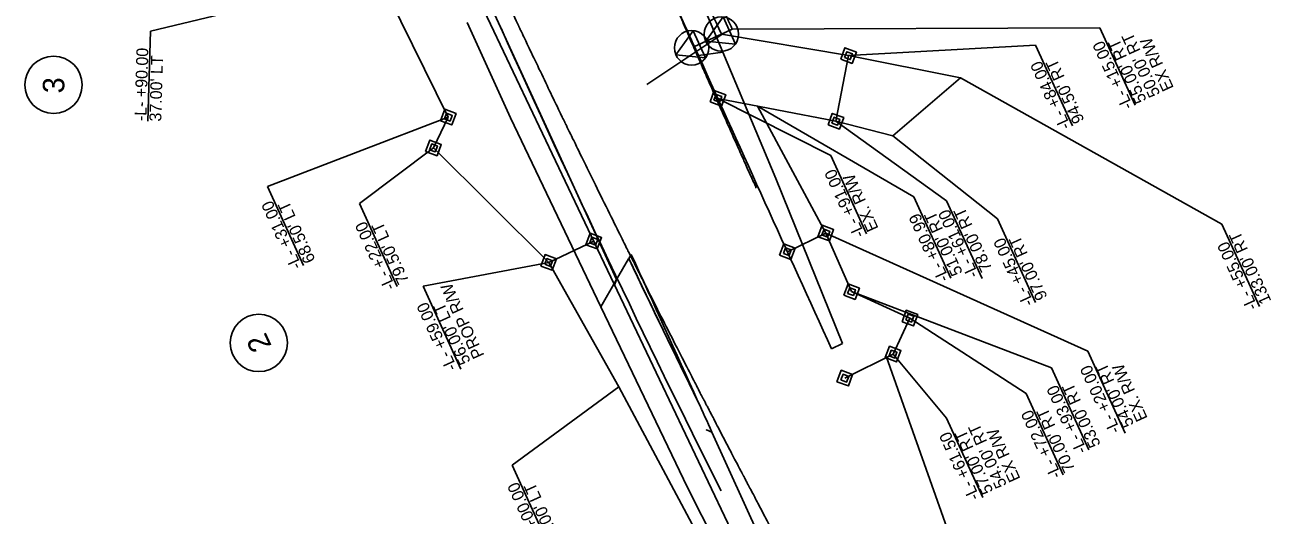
# Model space of a CAD drawing. Extents: x 2097272 to 2098144, y 685104 to 689282.
# Drawn here: x 2097622 to 2098144, y 685385 to 685590 of the extents above; entities that cross this region are included whole.
import ezdxf

# ---------------------------------------------------------------- set-up
doc = ezdxf.new("R2010")
doc.units = 0
for name, color, linetype in [('Prop Easement Construction', 7, 'Continuous'), ('Prop Easement Construction Station Offsets', 7, 'Continuous'), ('Prop Easement Permanent Drainage', 7, 'Continuous'), ('Prop Easement Permanent Drainage Station Offsets', 7, 'Continuous'), ('Prop Easement Permanent Utility', 7, 'Continuous'), ('Prop Easement Permanent Utility Station Offsets', 7, 'Continuous'), ('Prop Easement Temporary Drainage', 7, 'Continuous'), ('Prop Easement Temporary Drainage Station Offsets', 7, 'Continuous'), ('Prop Parcel Number CELL', 7, 'Continuous'), ('Prop ROW Marker CELL', 7, 'Continuous'), ('Prop ROW Permanent Easement CELL', 7, 'Continuous'), ('Prop ROW RW Lines', 7, 'Continuous'), ('Prop ROW Station Offsets', 7, 'Continuous'), ('Scratch_Level_1', 7, 'Continuous'), ('Scratch_Level_2', 7, 'Continuous'), ('Scratch_Level_3', 7, 'Continuous'), ('Scratch_Level_6', 7, 'Continuous')]:
    doc.layers.add(name, color=color, linetype=linetype)

msp = doc.modelspace()

# ---------------------------------------------------------------- linework, layer by layer
at = {"layer": 'Prop Easement Construction'}
for p, q in [((2097918.68, 685588.72), (2097914.13, 685586.63)), ((2097957.84, 685503.3), (2097929.21, 685556.51)), ((2097871.22, 685439.01), (2097841.77, 685491.03)), ((2098058, 685239.98), (2097983.31, 685451.34)), ((2097988.32, 685219.26), (2097871.22, 685439.01))]:
    msp.add_line(p, q, dxfattribs=at)
msp.add_arc((2102411.4, 687654.74), 4945, 204.4666, 204.69579, dxfattribs=at)
at = {"layer": 'Prop Easement Construction Station Offsets'}
for p, q in [((2098072.66, 685589.23), (2097918.68, 685588.72)), ((2098087.37, 685556.92), (2098072.66, 685589.23)), ((2097994.7, 685518.45), (2097929.21, 685556.51)), ((2098010.18, 685484.45), (2097994.7, 685518.45)), ((2097826.5, 685406.12), (2097871.22, 685439.01)), ((2097842.07, 685371.9), (2097826.5, 685406.12))]:
    msp.add_line(p, q, dxfattribs=at)
at = {"layer": 'Prop Easement Permanent Drainage'}
for p, q in [((2097967.36, 685577.63), (2097914.13, 685586.63)), ((2097962.04, 685550.15), (2097967.36, 685577.63)), ((2097912.63, 685559.72), (2097962.04, 685550.15))]:
    msp.add_line(p, q, dxfattribs=at)
at = {"layer": 'Prop Easement Permanent Drainage Station Offsets'}
for p, q in [((2098045.71, 685582.04), (2097967.36, 685577.63)), ((2098061.1, 685548.21), (2098045.71, 685582.04)), ((2097959.96, 685535.78), (2097912.63, 685559.72)), ((2098008.44, 685516.86), (2097962.04, 685550.15)), ((2097974.88, 685503), (2097959.96, 685535.78)), ((2098023.27, 685484.27), (2098008.44, 685516.86))]:
    msp.add_line(p, q, dxfattribs=at)
at = {"layer": 'Prop Easement Permanent Utility'}
for p, q in [((2097799.72, 685551.87), (2097768.52, 685614.96)), ((2097793.51, 685538.99), (2097799.72, 685551.87)), ((2097841.77, 685491.03), (2097793.51, 685538.99)), ((2097860.65, 685499.97), (2097841.77, 685491.03)), ((2097957.84, 685503.3), (2097941.74, 685495.52)), ((2097968.62, 685478.84), (2097957.84, 685503.3)), ((2097993.04, 685467.75), (2097968.62, 685478.84)), ((2097993.04, 685467.75), (2097986, 685452.68)), ((2097986, 685452.68), (2097965.79, 685442.62))]:
    msp.add_line(p, q, dxfattribs=at)
at = {"layer": 'Prop Easement Permanent Utility Station Offsets'}
for p, q in [((2097723.99, 685522.84), (2097799.72, 685551.87)), ((2097762.52, 685515.7), (2097793.51, 685538.99)), ((2097739.06, 685489.73), (2097723.99, 685522.84)), ((2097778.3, 685481.01), (2097762.52, 685515.7)), ((2098067.58, 685453.94), (2097957.84, 685503.3)), ((2097789.18, 685481.08), (2097841.77, 685491.03)), ((2097789.18, 685481.08), (2097804.96, 685446.4)), ((2098052.31, 685446.87), (2097968.62, 685478.84)), ((2098041.72, 685436.2), (2097993.04, 685467.75)), ((2098008.38, 685425.88), (2097986, 685452.68)), ((2098083.2, 685419.62), (2098067.58, 685453.94)), ((2098067.92, 685412.55), (2098052.31, 685446.87)), ((2098057.22, 685402.15), (2098041.72, 685436.2)), ((2098023.53, 685392.6), (2098008.38, 685425.88))]:
    msp.add_line(p, q, dxfattribs=at)
at = {"layer": 'Prop Easement Temporary Drainage'}
for p, q in [((2098014.26, 685568.39), (2097967.36, 685577.63)), ((2097985.95, 685544.11), (2098014.26, 685568.39)), ((2097962.04, 685550.15), (2097985.95, 685544.11))]:
    msp.add_line(p, q, dxfattribs=at)
at = {"layer": 'Prop Easement Temporary Drainage Station Offsets'}
for p, q in [((2098123.73, 685507.08), (2098014.26, 685568.39)), ((2098029.68, 685509.32), (2097985.95, 685544.11)), ((2098045.65, 685474.25), (2098029.68, 685509.32)), ((2098139.4, 685472.62), (2098123.73, 685507.08))]:
    msp.add_line(p, q, dxfattribs=at)
at = {"layer": 'Prop Parcel Number CELL'}
for centre in [(2097634.42, 685565.37), (2097720.37, 685457.35)]:
    msp.add_circle(centre, 12, dxfattribs=at)
at = {"layer": 'Prop ROW Marker CELL'}
for p, q in [((2097914.13, 685586.63), (2097914.13, 685586.63)), ((2097901.62, 685580.88), (2097901.62, 685580.88)), ((2097967.36, 685577.63), (2097967.36, 685577.63)), ((2097912.63, 685559.72), (2097912.63, 685559.72)), ((2097962.04, 685550.15), (2097962.04, 685550.15)), ((2097957.84, 685503.3), (2097957.84, 685503.3)), ((2097941.74, 685495.52), (2097941.74, 685495.52)), ((2097968.62, 685478.84), (2097968.62, 685478.84)), ((2097993.04, 685467.75), (2097993.04, 685467.75)), ((2097986, 685452.68), (2097986, 685452.68)), ((2097965.79, 685442.62), (2097965.79, 685442.62))]:
    msp.add_line(p, q, dxfattribs=at)
for points in [[(2097920, 685582.43), (2097907.58, 685583.65), (2097914.82, 685593.81)], [(2097907.49, 685576.68), (2097895.07, 685577.9), (2097902.31, 685588.06)]]:
    msp.add_lwpolyline(points, close=True, dxfattribs=at)
for centre in [(2097914.13, 685586.63), (2097901.62, 685580.88)]:
    msp.add_circle(centre, 7.2, dxfattribs=at)
at = {"layer": 'Prop ROW Permanent Easement CELL'}
for p, q in [((2097799.72, 685551.87), (2097799.72, 685551.87)), ((2097793.51, 685538.99), (2097793.51, 685538.99)), ((2097860.65, 685499.97), (2097860.65, 685499.97)), ((2097841.77, 685491.03), (2097841.77, 685491.03))]:
    msp.add_line(p, q, dxfattribs=at)
for points in [[(2097964.08, 685576.14), (2097965.86, 685580.91), (2097970.63, 685579.12), (2097968.85, 685574.35)], [(2097965.72, 685576.89), (2097966.61, 685579.27), (2097968.99, 685578.38), (2097968.1, 685575.99)], [(2097909.35, 685558.23), (2097911.13, 685563), (2097915.9, 685561.21), (2097914.12, 685556.44)], [(2097910.99, 685558.97), (2097911.88, 685561.36), (2097914.26, 685560.46), (2097913.37, 685558.08)], [(2097796.44, 685550.38), (2097798.23, 685555.15), (2097802.99, 685553.36), (2097801.21, 685548.59)], [(2097798.08, 685551.12), (2097798.97, 685553.51), (2097801.36, 685552.61), (2097800.46, 685550.23)], [(2097958.77, 685548.66), (2097960.55, 685553.43), (2097965.32, 685551.65), (2097963.53, 685546.88)], [(2097960.4, 685549.41), (2097961.3, 685551.79), (2097963.68, 685550.9), (2097962.79, 685548.52)], [(2097790.23, 685537.5), (2097792.02, 685542.27), (2097796.79, 685540.48), (2097795, 685535.71)], [(2097791.87, 685538.24), (2097792.77, 685540.63), (2097795.15, 685539.73), (2097794.26, 685537.35)], [(2097954.56, 685501.81), (2097956.35, 685506.58), (2097961.11, 685504.79), (2097959.33, 685500.03)], [(2097956.2, 685502.56), (2097957.09, 685504.94), (2097959.48, 685504.05), (2097958.58, 685501.66)], [(2097857.38, 685498.48), (2097859.16, 685503.25), (2097863.93, 685501.46), (2097862.14, 685496.69)], [(2097859.01, 685499.22), (2097859.91, 685501.61), (2097862.29, 685500.71), (2097861.4, 685498.33)], [(2097838.5, 685489.54), (2097840.28, 685494.31), (2097845.05, 685492.52), (2097843.27, 685487.75)], [(2097938.46, 685494.03), (2097940.25, 685498.8), (2097945.01, 685497.01), (2097943.23, 685492.25)], [(2097940.1, 685494.78), (2097940.99, 685497.16), (2097943.37, 685496.27), (2097942.48, 685493.89)], [(2097840.14, 685490.28), (2097841.03, 685492.67), (2097843.41, 685491.78), (2097842.52, 685489.39)], [(2097965.35, 685477.35), (2097967.13, 685482.12), (2097971.9, 685480.33), (2097970.11, 685475.57)], [(2097966.98, 685478.1), (2097967.88, 685480.48), (2097970.26, 685479.59), (2097969.37, 685477.21)], [(2097989.76, 685466.25), (2097991.55, 685471.02), (2097996.31, 685469.24), (2097994.53, 685464.47)], [(2097991.4, 685467), (2097992.29, 685469.38), (2097994.67, 685468.49), (2097993.78, 685466.11)], [(2097982.72, 685451.19), (2097984.51, 685455.96), (2097989.28, 685454.17), (2097987.49, 685449.4)], [(2097984.36, 685451.93), (2097985.25, 685454.32), (2097987.64, 685453.43), (2097986.75, 685451.04)], [(2097962.51, 685441.13), (2097964.29, 685445.9), (2097969.06, 685444.11), (2097967.28, 685439.34)], [(2097964.15, 685441.88), (2097965.04, 685444.26), (2097967.42, 685443.37), (2097966.53, 685440.98)]]:
    msp.add_lwpolyline(points, close=True, dxfattribs=at)
at = {"layer": 'Prop ROW RW Lines'}
for p, q in [((2097931.37, 685351.45), (2097804.03, 685618.88)), ((2097914.13, 685586.63), (2097902.8, 685581.42))]:
    msp.add_line(p, q, dxfattribs=at)
msp.add_arc((2102411.4, 687654.74), 4950, 204.23092, 204.69579, dxfattribs=at)
at = {"layer": 'Prop ROW Station Offsets'}
for p, q in [((2097674.97, 685587.86), (2097804.03, 685618.88)), ((2097673.87, 685550.15), (2097674.97, 685587.86))]:
    msp.add_line(p, q, dxfattribs=at)
at = {"layer": 'Scratch_Level_1'}
for points in [[(2097849.36, 685547.98), (2097849.36, 685547.98), (2097849.36, 685547.99)], [(2097877.96, 685490.04), (2097877.96, 685490.04), (2097877.95, 685490.04)], [(2097907.28, 685432.49), (2097907.28, 685432.49), (2097907.28, 685432.49)]]:
    msp.add_lwpolyline(points, dxfattribs=at)
msp.add_arc((2102411.4, 687654.74), 5033, 204.23092, 206.6729, dxfattribs=at)
for points in [[(2097905.75, 685573.76), (2097905.68, 685573.91), (2097905.58, 685574.14), (2097905.48, 685574.37), (2097905.41, 685574.52), (2097905.38, 685574.6), (2097905.28, 685574.83), (2097905.21, 685574.98), (2097905.13, 685575.17), (2097905.11, 685575.21), (2097905.09, 685575.27), (2097905.08, 685575.29), (2097905.06, 685575.32), (2097905.06, 685575.33), (2097905.05, 685575.35), (2097905.05, 685575.35), (2097905.01, 685575.44), (2097904.98, 685575.52), (2097904.68, 685576.2), (2097904.41, 685576.81), (2097903.61, 685578.64), (2097903.08, 685579.86), (2097901.48, 685583.52), (2097898.29, 685590.84), (2097895.12, 685598.16), (2097891.97, 685605.5), (2097890.92, 685607.94), (2097889.34, 685611.61), (2097888.82, 685612.83), (2097888.17, 685614.36), (2097888.03, 685614.67), (2097887.84, 685615.13), (2097887.77, 685615.28), (2097887.69, 685615.47), (2097887.67, 685615.53), (2097887.64, 685615.6), (2097887.63, 685615.63), (2097887.62, 685615.64), (2097887.61, 685615.65), (2097887.59, 685615.7), (2097887.58, 685615.74), (2097887.55, 685615.8), (2097887.54, 685615.82), (2097887.53, 685615.85), (2097887.52, 685615.87), (2097887.52, 685615.88), (2097887.45, 685616.04), (2097887.38, 685616.2), (2097887.25, 685616.5), (2097887.19, 685616.66), (2097886.99, 685617.11), (2097886.86, 685617.42), (2097884.63, 685622.64), (2097882.53, 685627.56), (2097880.43, 685632.47)], [(2097849.36, 685547.99), (2097849.22, 685548.29), (2097849.07, 685548.59), (2097848.85, 685549.04), (2097848.76, 685549.23), (2097848.67, 685549.42), (2097848.63, 685549.5), (2097848.61, 685549.54), (2097848.56, 685549.65), (2097848.23, 685550.33), (2097847.31, 685552.22), (2097845.26, 685556.46), (2097841.17, 685564.94), (2097836.51, 685574.64), (2097832.46, 685583.14), (2097830.59, 685587.09), (2097829.79, 685588.76), (2097829.54, 685589.3), (2097829.41, 685589.56), (2097829.36, 685589.68), (2097829.32, 685589.75), (2097829.31, 685589.79), (2097829.14, 685590.13), (2097829, 685590.44), (2097828.71, 685591.04), (2097828.57, 685591.35), (2097826.12, 685596.51), (2097823.82, 685601.36), (2097821.53, 685606.22)], [(2097928.72, 685522.14), (2097928.6, 685522.41), (2097928.48, 685522.68), (2097928.24, 685523.21), (2097927.87, 685524.02), (2097927.03, 685525.9), (2097926.3, 685527.51), (2097924.85, 685530.72), (2097923.89, 685532.87), (2097921, 685539.32), (2097917.16, 685547.91), (2097912.86, 685557.6), (2097910.49, 685562.98), (2097909.54, 685565.14), (2097909.06, 685566.21), (2097908.35, 685567.83), (2097908.11, 685568.37), (2097907.64, 685569.45), (2097907.4, 685569.98), (2097907.05, 685570.79), (2097906.93, 685571.06), (2097906.69, 685571.6), (2097906.58, 685571.87), (2097906.22, 685572.68), (2097905.98, 685573.22), (2097905.75, 685573.76)], [(2097877.95, 685490.04), (2097877.8, 685490.35), (2097877.65, 685490.65), (2097877.43, 685491.1), (2097877.33, 685491.29), (2097877.24, 685491.47), (2097877.2, 685491.55), (2097877.18, 685491.59), (2097877.13, 685491.7), (2097876.79, 685492.38), (2097875.84, 685494.26), (2097873.74, 685498.47), (2097869.53, 685506.9), (2097863.56, 685518.96), (2097857.62, 685531.05), (2097853.49, 685539.51), (2097851.42, 685543.75), (2097850.54, 685545.56), (2097849.95, 685546.77), (2097849.66, 685547.38), (2097849.36, 685547.98)], [(2097907.28, 685432.49), (2097907.13, 685432.79), (2097906.97, 685433.09), (2097906.74, 685433.54), (2097906.64, 685433.72), (2097906.55, 685433.91), (2097906.51, 685433.98), (2097906.49, 685434.02), (2097906.43, 685434.13), (2097906.08, 685434.81), (2097905.12, 685436.67), (2097902.96, 685440.86), (2097898.65, 685449.24), (2097892.52, 685461.22), (2097886.43, 685473.22), (2097882.18, 685481.63), (2097880.07, 685485.83), (2097879.16, 685487.64), (2097878.56, 685488.84), (2097878.26, 685489.44), (2097877.96, 685490.04)], [(2097937.09, 685375.47), (2097936.93, 685375.77), (2097936.78, 685376.07), (2097936.55, 685376.51), (2097936.47, 685376.66), (2097936.35, 685376.88), (2097936.32, 685376.96), (2097936.24, 685377.11), (2097935.89, 685377.78), (2097934.93, 685379.63), (2097932.76, 685383.78), (2097929.66, 685389.71), (2097927.02, 685394.74), (2097925.62, 685397.41), (2097925.31, 685398), (2097925.15, 685398.3), (2097924.68, 685399.18), (2097924.37, 685399.78), (2097923.9, 685400.67), (2097923.74, 685400.96), (2097923.43, 685401.56), (2097923.28, 685401.85), (2097923.08, 685402.22), (2097923.04, 685402.3), (2097922.96, 685402.45), (2097922.85, 685402.67), (2097922.57, 685403.19), (2097919.84, 685408.39), (2097915.95, 685415.82), (2097911.61, 685424.15), (2097909.44, 685428.32), (2097908.52, 685430.11), (2097907.9, 685431.3), (2097907.59, 685431.89), (2097907.28, 685432.49)]]:
    msp.add_open_spline(points, degree=3, dxfattribs=at)
at = {"layer": 'Scratch_Level_2'}
msp.add_line((2097915.48, 685587.25), (2097882.85, 685565.52), dxfattribs=at)
at = {"layer": 'Scratch_Level_3'}
msp.add_line((2097876.35, 685494.42), (2097875.32, 685492.66), dxfattribs=at)
for centre, radius, start, end in [((2162207.31, 714677.79), 70580.94, 204.221202, 204.3376459), ((2162207.31, 714677.79), 70640.94, 204.4011483, 204.4559512), ((2102411.4, 687654.74), 5025, 205.48445, 206.24164)]:
    msp.add_arc(centre, radius, start, end, dxfattribs=at)
at = {"layer": 'Scratch_Level_6'}
for p, q in [((2097914.75, 685579.02), (2097879.27, 685663.71)), ((2097870.23, 685483.9), (2097818.43, 685596.49)), ((2097807.67, 685591.54), (2097825.72, 685551.52)), ((2097904.53, 685577.6), (2097914.75, 685579.02)), ((2097914.75, 685579.02), (2097904.53, 685577.6)), ((2097936.88, 685526.2), (2097914.75, 685579.02)), ((2097825.72, 685551.52), (2097863.6, 685472.5)), ((2097964.83, 685457.1), (2097936.88, 685526.2)), ((2097875.26, 685492.55), (2097870.23, 685483.9)), ((2097870.23, 685483.9), (2097863.6, 685472.5)), ((2097863.6, 685472.5), (2097870.23, 685483.9)), ((2097863.6, 685472.5), (2097899.86, 685396.86)), ((2097960.23, 685454.83), (2097964.83, 685457.1)), ((2097899.86, 685396.86), (2097990.14, 685220.09))]:
    msp.add_line(p, q, dxfattribs=at)
for points in [[(2097870.23, 685483.9), (2097869.36, 685481.55), (2097870.23, 685483.9)], [(2097910.14, 685420.03), (2097907.8, 685420.91), (2097910.14, 685420.03)], [(2098051.01, 685110.46), (2097957.82, 685315.25), (2097910.14, 685420.03)]]:
    msp.add_lwpolyline(points, dxfattribs=at)
for centre, radius, start, end in [((2162207.31, 714677.79), 70580.94, 204.3376459, 204.3491039), ((2162207.31, 714677.79), 70580.94, 204.3491039, 204.4585453), ((2097876.37, 685494.45), 2.2, 239.8285, 244.3187), ((2102411.4, 687654.74), 5025, 205.48683, 206.24164), ((2162207.31, 714677.79), 70640.94, 204.4559512, 204.4674158)]:
    msp.add_arc(centre, radius, start, end, dxfattribs=at)

# ---------------------------------------------------------------- texts
at = {"layer": 'Prop Easement Construction Station Offsets'}
for s, p in [('-L- +15.00', (2098086.61, 685556.37)), ("55.00' RT", (2098092.3, 685558.96)), ("50.00' RT", (2098097.99, 685561.55)), ('EX R/W', (2098103.68, 685564.14)), ('-L- +80.99', (2098009.61, 685484.19)), ("51.00' RT", (2098015.3, 685486.78)), ('-L- +00.00', (2097841.5, 685371.64)), ("52.00' LT", (2097847.19, 685374.23))]:
    msp.add_text(s, height=5, rotation=114.4674, dxfattribs=at).set_placement(p)
at = {"layer": 'Prop Easement Permanent Drainage Station Offsets'}
for s, p in [('-L- +84.00', (2098060.53, 685547.95)), ("94.50' RT", (2098066.22, 685550.54)), ('-L- +91.00', (2097974.31, 685502.74)), ('EX. R/W', (2097980, 685505.33)), ('-L- +61.00', (2098021.93, 685485.85)), ("78.00' RT", (2098027.62, 685488.44))]:
    msp.add_text(s, height=5, rotation=114.4674, dxfattribs=at).set_placement(p)
at = {"layer": 'Prop Easement Permanent Utility Station Offsets'}
for s, p in [('-L- +31.00', (2097738.49, 685489.47)), ("68.50' LT", (2097744.18, 685492.06)), ('-L- +22.00', (2097777.73, 685480.76)), ("79.50' LT", (2097783.42, 685483.34)), ('PROP R/W', (2097814.9, 685452.16)), ('-L- +59.00', (2097803.52, 685446.98)), ("56.00' LT", (2097809.21, 685449.57)), ('-L- +20.00', (2098081.34, 685420.7)), ("54.00' RT", (2098087.02, 685423.29)), ('EX. R/W', (2098092.71, 685425.87)), ('-L- +93.00', (2098067.35, 685412.29)), ("53.00' RT", (2098073.04, 685414.88)), ('-L- +72.00', (2098056.65, 685401.89)), ("70.00' RT", (2098062.34, 685404.48)), ("54.00' RT", (2098033.76, 685397.92)), ('-L- +61.50', (2098022.38, 685392.75)), ("57.00' RT", (2098028.07, 685395.34)), ('EX R/W', (2098039.45, 685400.51))]:
    msp.add_text(s, height=5, rotation=114.4674, dxfattribs=at).set_placement(p)
at = {"layer": 'Prop Easement Temporary Drainage Station Offsets'}
for s, p in [('-L- +45.00', (2098045.08, 685473.99)), ("97.00' RT", (2098050.77, 685476.58)), ('-L- +55.00', (2098138.83, 685472.36)), ("133.00' RT", (2098144.52, 685474.95))]:
    msp.add_text(s, height=5, rotation=114.4674, dxfattribs=at).set_placement(p)
at = {"layer": 'Prop Parcel Number CELL'}
for s, rotation, p in [('3', 88.3348, (2097638.82, 685561.73)), ('2', 114.647, (2097725.89, 685456.11))]:
    msp.add_text(s, height=9, rotation=rotation, dxfattribs=at).set_placement(p)
at = {"layer": 'Prop ROW Station Offsets'}
for s, p in [('-L- +90.00', (2097673.25, 685550.16)), ("37.00' LT", (2097679.5, 685549.98))]:
    msp.add_text(s, height=5, rotation=88.3348, dxfattribs=at).set_placement(p)

doc.saveas('drawing.dxf')
